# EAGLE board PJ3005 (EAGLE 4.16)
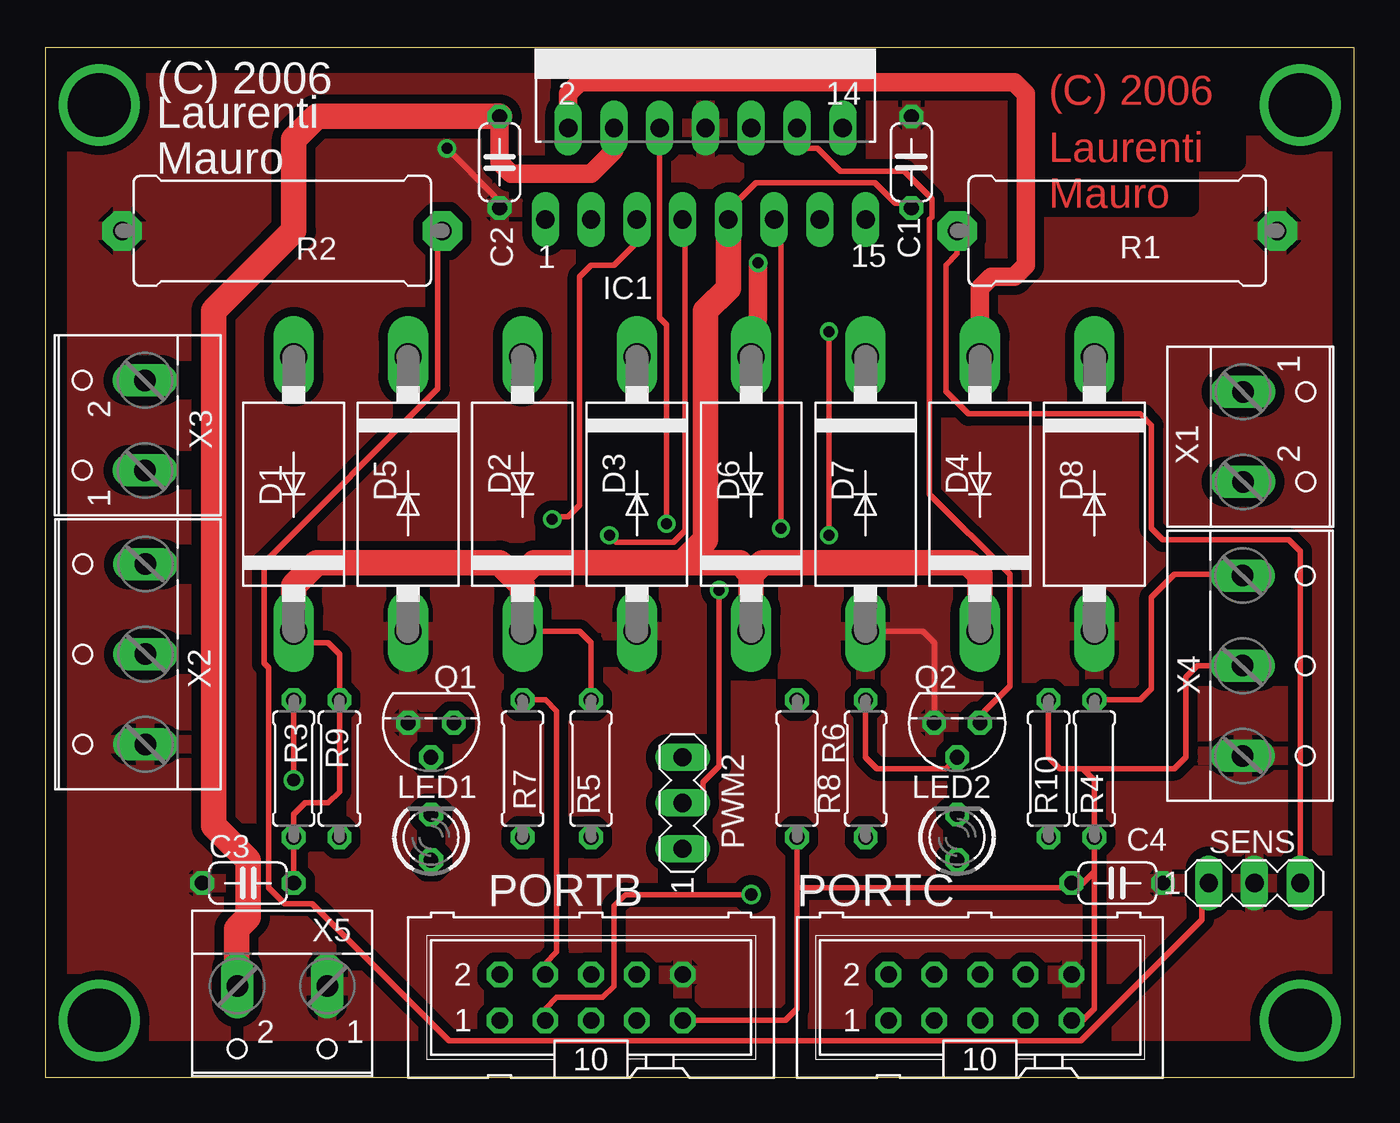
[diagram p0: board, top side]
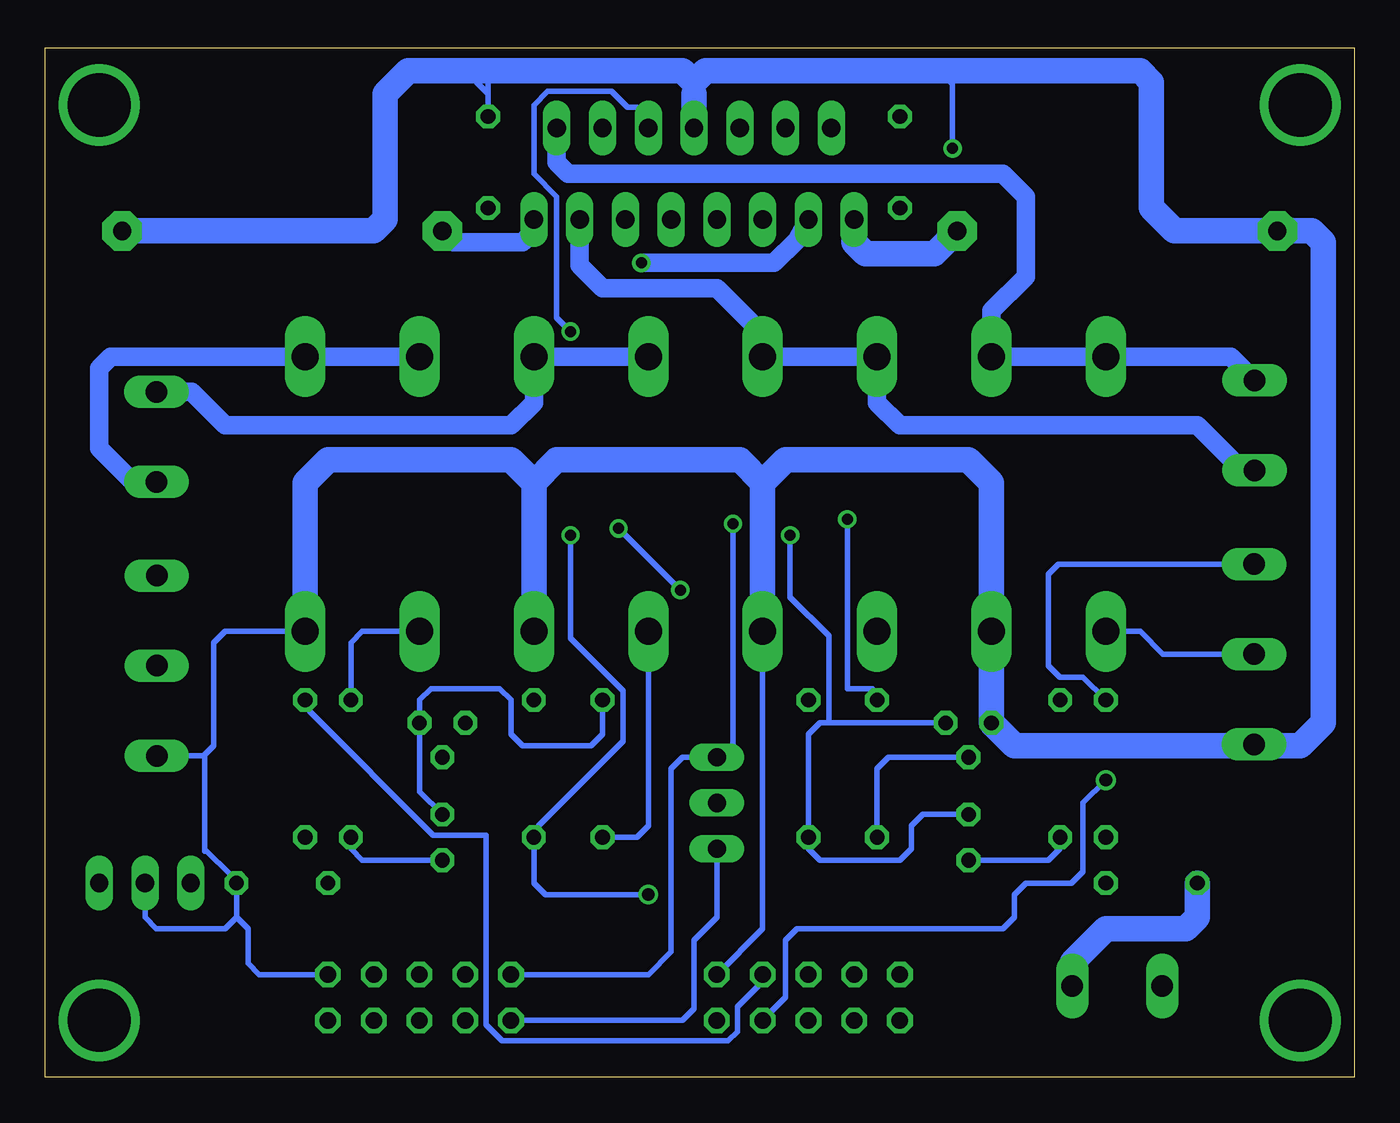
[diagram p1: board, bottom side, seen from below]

Size 72.69 x 57.14 mm. Coordinates in mm from the lower left corner, seen from the top.
Outline: 0,0 72.69,0 72.69,57.14 0,57.14 0,0
Copper layers (1*16): Top 0.035mm / dielectric 1.5mm / Bottom 0.035mm
Design rules "default": minimum track width 12mil, minimum drill 24mil, track to track 20mil, track to pad 11mil, pad to pad 11mil, via to via 11mil, smd to smd 8mil, copper to edge 40mil, drill to drill 8mil, minimum pad ring 10mil, minimum via ring 8mil, stop-mask expansion 4mil, vias tented up to drill 0mil, thermal gap 10mil

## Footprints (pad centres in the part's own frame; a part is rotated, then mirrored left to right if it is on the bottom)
C050-024X044 = drill 0.813 octagon: 1 -2.54,0; 2 2.54,0
DO201-15 = drill 1.499 long: A 7.62,0; C -7.62,0
MULTIWATT-15 = drill 1.016 long: 1 -8.89,-7.62; 2 -7.62,-2.54; 3 -6.35,-7.62; 4 -5.08,-2.54; 5 -3.81,-7.62; 6 -2.54,-2.54; 7 -1.27,-7.62; 8 0,-2.54; 9 1.27,-7.62; 10 2.54,-2.54; 11 3.81,-7.62; 12 5.08,-2.54; 13 6.35,-7.62; 14 7.62,-2.54; 15 8.89,-7.62
LED3MM = drill 0.813 octagon: A -1.27,0; K 1.27,0
ML10 = drill 0.914 octagon: 1 -5.08,-1.27; 2 -5.08,1.27; 3 -2.54,-1.27; 4 -2.54,1.27; 5 0,-1.27; 6 0,1.27; 7 2.54,-1.27; 8 2.54,1.27; 9 5.08,-1.27; 10 5.08,1.27
MA03-1 = drill 1.016 long: 1 -2.54,0; 2 0,0; 3 2.54,0
TO92 = drill 0.813 octagon: 1 1.27,0; 2 0,1.905; 3 -1.27,0
0617/17 = drill 1.016 pad 2.184 octagon: 1 -8.89,0; 2 8.89,0
0207/7 = drill 0.813 octagon: 1 -3.81,0; 2 3.81,0
W237-102 = drill 1.194 long: 1 -2.5,-1.27; 2 2.5,-1.27
W237-103 = drill 1.194 long: 1 -5,-1.29; 2 0,-1.29; 3 5,-1.29

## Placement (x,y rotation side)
C1  0.1uF  [C050-024X044]  48.1,50.8 90 top
C2  0.1uF  [C050-024X044]  25.23,50.8 270 top
C3  0.1uF  [C050-024X044]  11.27,10.79 0 top
C4  0.1uF  [C050-024X044]  59.52,10.79 180 top
D1  FR303  [DO201-15]  13.8,32.38 90 top
D2  FR303  [DO201-15]  26.5,32.38 90 top
D3  FR303  [DO201-15]  39.21,32.38 90 top
D4  FR303  [DO201-15]  51.91,32.38 90 top
D5  FR303  [DO201-15]  20.15,32.38 270 top
D6  FR303  [DO201-15]  32.86,32.38 270 top
D7  FR303  [DO201-15]  45.55,32.38 270 top
D8  FR303  [DO201-15]  58.26,32.38 270 top
IC1  L298  [MULTIWATT-15]  36.66,55.24 0 top
LED1  [LED3MM]  21.43,13.33 90 top
LED2  [LED3MM]  50.64,13.33 90 top
PORTB  [ML10]  30.32,4.44 0 top
PORTC  [ML10]  51.91,4.44 0 top
PWM2  [MA03-1]  35.4,15.23 90 top
Q1  BC337  [TO92]  21.43,19.68 180 top
Q2  BC337  [TO92]  50.64,19.68 180 top
R1  0.22  [0617/17]  59.52,46.98 180 top
R2  0.22  [0617/17]  13.17,46.98 0 top
R3  10K  [0207/7]  13.8,17.14 270 top
R4  10K  [0207/7]  58.26,17.14 90 top
R5  10K  [0207/7]  30.32,17.14 90 top
R6  10K  [0207/7]  41.75,17.14 270 top
R7  4.7K  [0207/7]  26.5,17.14 270 top
R8  4.7K  [0207/7]  45.55,17.14 90 top
R9  330  [0207/7]  16.34,17.14 90 top
R10  330  [0207/7]  55.72,17.14 90 top
SENS  [MA03-1]  67.14,10.79 0 top
X1  [W237-102]  67.78,35.55 270 top
X2  [W237-103]  4.28,23.49 90 top
X3  [W237-102]  4.28,36.19 90 top
X4  [W237-103]  67.78,22.86 270 top
X5  [W237-102]  13.17,3.8 180 top

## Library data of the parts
C1-C4 R1-R10 = rcl
D1-D8 = diode
IC1 = st-microelectronics
LED1 LED2 = led
PORTB PORTC = con-harting-ml
PWM2 SENS = con-lstb
Q1 Q2 = transistor-npn
X1-X5 = con-wago-500

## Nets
GND: C1.2 C2.2 C3.1 C4.1 D5.A D6.A D7.A D8.A IC1.8 PORTB.10 PORTC.10 Q1.1 Q2.1 R1.1 R2.1 SENS.2 X2.1 X4.3 X5.1
N$1: IC1.1 R2.2 SENS.1
N$2: IC1.15 R1.2 SENS.3
N$3: C2.1 IC1.4 X5.2
N$5: LED2.A R10.1
N$6: LED1.A R9.1
N$8: IC1.6 PORTC.2 PWM2.3
N$9: IC1.11 PWM2.2
N$10: PORTC.1 PWM2.1
N$11: IC1.7 LED1.K Q1.3 R5.1
N$12: PORTB.7 R3.1 X2.3
N$13: PORTB.8 R4.2 X4.1
N$14: IC1.12 LED2.K Q2.3 R6.1
N$15: Q2.2 R8.2
N$16: Q1.2 R7.2
N$17: IC1.5 PORTB.4 R7.1
N$18: IC1.10 PORTB.3 R8.1
N$20: D2.A D6.C IC1.13 X3.1
N$21: D4.A D8.C IC1.2 X1.2
N$22: D1.A D5.C IC1.14 X3.2
N$23: D3.A D7.C IC1.3 X1.1
VCC: C1.1 C3.2 C4.2 D1.C D2.C D3.C D4.C IC1.9 PORTB.9 PORTC.9 R3.2 R4.1 R5.2 R6.2 R9.2 R10.2 X2.2 X4.2

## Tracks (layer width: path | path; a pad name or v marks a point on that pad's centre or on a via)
GND  (via drill 0.61)
  Top 0.305: Q2.1 49.37,24.12 48.73,24.76 D7.A | v22.31,51.56 24.98,48.89 C2.2
  Bottom 0.305: 63.89,17.86 X4.3 | 63.89,17.86 63.34,18.41 63.34,24.12 62.7,24.76 D8.A | 62.07,8.88 C4.1 62.45,11.3 63.72,12.57 63.84,12.57 63.84,17.77 63.89,17.86 | 62.07,8.88 61.43,8.25 61.43,6.34 60.8,5.71 PORTC.10 | 48.1,54.61 C1.2 | 48.1,54.61 48.73,55.24 48.73,55.88 | Q1.1 19.52,19.68 | PORTB.10 32.86,8.25 D6.A | SENS.2 67.14,8.88 66.51,8.25 62.7,8.25 62.07,8.88 | 22.31,55.62 v22.31,51.56 | 22.31,55.62 22.31,55.88 | 22.44,55.49 22.44,55.62 22.31,55.62 | 22.44,55.49 22.44,55.24 | 36.66,55.24 36.66,54.61 | 48.1,55.88 48.1,54.61 | 22.57,55.88 22.57,55.49 22.44,55.49
  Bottom 1.422: D6.A 32.86,24.12 | D6.A 32.86,27.3 | 5.55,18.41 5.57,18.43 X2.1 | 5.55,18.41 6.18,18.41 | 4.92,18.41 5.55,18.41 | 4.92,18.41 3.01,18.41 1.74,19.68 1.74,46.35 2.38,46.98 R2.1 10,46.98 11.27,48.25 11.27,55.24 11.9,55.88 22.57,55.88 36.03,55.88 36.66,55.24 37.3,55.88 48.1,55.88 52.54,55.88 53.81,54.61 53.81,47.62 54.45,46.98 R1.1 | 36.66,54.61 IC1.8 | 4.92,18.41 18.88,18.41 Q1.1 D5.A 20.15,33.02 21.43,34.28 31.58,34.28 32.86,33.02 | 32.86,33.02 D6.A | 45.55,33.02 D7.A | 45.55,33.02 44.29,34.28 34.12,34.28 32.86,33.02 | D8.A 58.26,33.02 56.98,34.28 46.83,34.28 45.55,33.02 | X5.1 15.67,6.38 13.8,8.25 9.36,8.25 8.73,8.88 C3.1
  pour Top: 3.01,55.24 70.95,55.24 70.95,2.54 1.74,2.54 1.74,55.24
N$1
  Top 0.305: SENS.1 64.22,9.39 64.22,8.76 57.49,2.03 22.44,2.03 14.82,9.65 13.3,9.65 12.41,10.54 12.41,22.73 12.15,22.98 12.15,28.57 21.81,38.22 21.81,46.73 R2.2
  Bottom 1.422: IC1.1 27.78,46.35 27.14,45.72 23.33,45.72 R2.2
N$2
  Top 0.305: SENS.3 69.69,29.21 69.05,29.84 62.07,29.84 61.43,30.47 61.43,36.19 60.8,36.83 51.27,36.83 50,38.09 50,45.08 50.64,45.72 R1.2
  Bottom 1.016: R1.2 50,46.35 46.19,46.35 45.55,46.98 IC1.15
N$3
  Top 1.016: IC1.4 31.58,51.43 30.32,50.16 25.87,50.16 25.23,50.8 C2.1
  Top 1.422: C2.1 15.07,53.34 13.8,52.06 13.8,46.98 9.36,42.54 9.36,13.96 11.27,12.06 11.27,8.88 10.63,8.25 10.63,5.07 X5.2
N$4  (via drill 3.5)
  other vias: 3.01,53.97
N$5
  Bottom 0.305: LED2.A 55.08,12.06 55.72,12.7 R10.1
N$6
  Bottom 0.305: LED1.A 16.98,12.06 16.34,12.7 R9.1
N$7  (via drill 3.5)
  other vias: 69.69,53.97
N$8  (via drill 0.61)
  Top 0.305: v34.51,30.73 34.51,41.78 34.12,42.16 IC1.6
  Bottom 0.305: PORTC.2 39.21,5.71 37.94,6.98 37.94,17.14 37.3,17.77 PWM2.3 34.51,18.41 v34.51,30.73
N$9  (via drill 0.61)
  Top 0.305: v37.43,27.05 37.43,17.27 36.54,16.38 36.54,15.87 PWM2.2 | v40.86,30.47 40.86,46.22 IC1.11
  Bottom 0.305: v37.43,27.05 v40.86,30.47
N$10
  Bottom 0.305: 40.48,3.17 39.84,3.17 | 40.48,3.17 PORTC.1 | PWM2.1 35.4,8.88 36.66,7.61 36.66,3.8 37.3,3.17 40.48,3.17
N$11  (via drill 0.61)
  Top 0.305: v31.33,30.09 31.71,29.71 34.89,29.71 35.52,30.35 35.52,46.22 IC1.7
  Bottom 0.305: 29.17,19.68 29.68,19.68 30.32,19.04 R5.1 30.32,12.7 29.68,12.06 25.23,12.06 24.6,12.7 24.6,13.96 23.96,14.6 LED1.K | 29.17,19.68 Q1.3 | v31.33,30.09 31.33,26.67 29.17,24.51 29.17,19.68
N$12  (via drill 0.7)
  Top 0.305: v13.8,16.5 R3.1
  Bottom 0.305: X2.3 16.43,28.49 16.98,27.93 16.98,22.86 16.34,22.22 15.07,22.22 R3.1 | PORTB.7 31.58,4.44 31.58,7.61 30.95,8.25 19.52,8.25 18.88,8.88 18.88,10.15 18.25,10.79 15.71,10.79 15.07,11.43 15.07,15.23 v13.8,16.5
N$13
  Top 0.305: R4.2 60.8,20.95 61.43,21.58 61.43,26.67 62.7,27.93 66.51,27.93 66.49,27.92 X4.1
  Bottom 0.305: PORTB.8 33.11,5.07 34.25,3.93 34.25,2.55 34.78,2.03 47.33,2.03 48.22,2.92 48.22,13.46 51.14,13.46 58,20.31 R4.2
N$14
  Top 0.305: IC1.12 42.38,51.56 42.89,51.56 44.16,50.29 47.71,50.29 49.24,48.76 49.24,47.75 49.11,47.62 49.11,32.38 53.56,27.93 53.56,21.71 52.16,20.31 Q2.3
  Bottom 0.305: R6.1 41.75,19.04 42.38,18.41 46.19,18.41 46.83,19.04 46.83,20.95 47.46,21.58 51.27,21.58 51.91,20.95 Q2.3 51.91,15.87 LED2.K
N$15
  Top 0.305: R8.2 45.55,17.77 46.19,17.14 50,17.14 Q2.2
N$16
  Bottom 0.305: Q1.2 25.87,17.77 26.5,17.14 R7.2
N$17  (via drill 0.61)
  Top 0.305: R7.1 27.78,20.95 28.41,20.31 28.41,6.98 27.78,6.34 PORTB.4 | IC1.5 32.86,46.35 31.58,45.08 30.32,45.08 29.68,44.44 29.68,31.75 29.04,31.11 28.41,31.11 28.28,30.98 v28.16,30.98
  Bottom 0.305: v28.16,30.98 28.16,21.58 26.76,21.58 R7.1
N$18  (via drill 0.61, 0.7)
  Top 0.305: PORTB.3 27.78,3.8 28.41,4.44 30.95,4.44 31.58,5.07 31.58,9.52 32.22,10.15 v39.21,10.15 | v43.52,30.09 v43.52,41.4
  Bottom 0.305: v39.21,10.15 44.92,10.15 45.55,10.79 R8.1 45.3,13.96 40.6,18.66 40.6,21.46 43.52,24.38 v43.52,30.09 | v43.52,41.4 44.29,42.16 44.29,48.89 45.55,50.16 45.55,53.97 44.79,54.73 41.24,54.73 40.35,53.84 39.84,53.84 IC1.10
N$19  (via drill 3.5)
  other vias: 3.01,3.17
N$20
  Bottom 1.016: X3.1 5.55,33.65 6.18,33.65 8.73,36.19 25.23,36.19 26.5,37.46 D2.A D6.C 32.86,41.27 35.4,43.81 41.75,43.81 43.02,45.08 IC1.13
N$21
  Top 1.016: IC1.2 29.04,54.61 29.68,55.24 53.81,55.24 54.45,54.61 54.45,45.08 53.81,44.44 52.54,44.44 51.91,43.81 D4.A
  Bottom 1.016: D4.A D8.C 69.05,40 69.69,39.36 69.69,34.92 67.82,33.05 X1.2
N$22
  Bottom 1.016: X3.2 6.86,40 D1.A D5.C 20.15,42.54 18.25,44.44 18.25,48.89 19.52,50.16 43.65,50.16 44.29,50.8 IC1.14
N$23  (via drill 0.61)
  Top 1.016: v39.59,45.21 39.59,42.16 D3.A
  Bottom 1.016: D3.A D7.C 45.55,37.46 46.83,36.19 62.7,36.19 64.56,38.05 X1.1 | v39.59,45.21 32.22,45.21 30.95,46.48 IC1.3
N$24  (via drill 3.5)
  other vias: 69.69,3.17
VCC
  Top 0.305: D1.C 13.8,24.12 15.71,24.12 16.34,23.49 R9.2 16.34,15.87 15.71,15.23 14.44,15.23 13.8,14.6 R3.2 C3.2 | R5.2 30.32,24.12 29.68,24.76 D2.C | R10.2 55.72,17.77 56.35,17.14 57.62,17.14 | 57.62,17.14 58.26,16.5 R4.1 58.26,11.43 | 58.26,11.43 57.62,10.79 C4.2 56.35,10.54 41.75,10.54 | PORTC.9 57.62,3.17 58.26,3.8 58.26,11.43 | 66.51,22.86 X4.2 63.97,22.86 63.34,22.22 63.34,17.77 62.7,17.14 57.62,17.14 | PORTB.9 41.11,3.17 41.75,3.8 41.75,10.54 | R6.2 41.75,10.54 | C1.1 47.46,48.51 47.21,48.51 46.06,49.65 39.46,49.65 38.57,48.76 IC1.9
  Top 1.422: D2.C 26.5,27.3 26.19,27.62 | 26.19,27.62 25.23,28.57 15.07,28.57 13.8,27.3 D1.C | 39.21,27.93 38.57,28.57 35.4,28.57 | 35.4,28.57 27.14,28.57 26.19,27.62 | 39.21,27.93 D3.C | 39.21,27.93 39.84,28.57 51.27,28.57 51.91,27.93 D4.C | IC1.9 37.94,43.81 36.66,42.54 36.66,29.84 35.4,28.57
  Bottom 0.305: R6.2 39.84,13.33 39.21,13.96 D3.C | X2.2 10.63,23.49 11.9,24.76 D1.C | R10.2 55.72,24.12 55.08,24.76 51.27,24.76

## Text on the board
Top: (C) 2006 | Laurenti | Mauro
tPlace: (C) 2006 | Laurenti | Mauro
